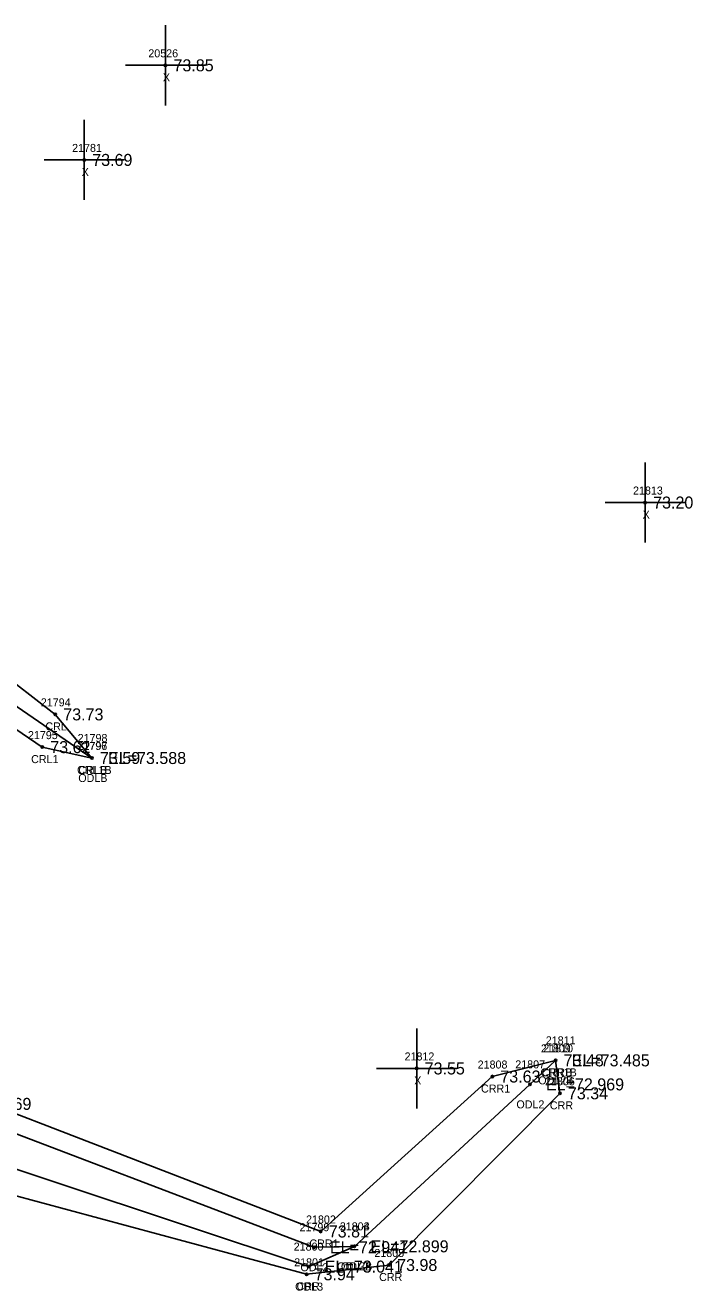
# Model space of a CAD drawing. Extents: x 2140110 to 2141565, y 506241 to 510327.
# Drawn here: x 2141122 to 2141205.4, y 508987.8 to 509145.9 of the extents above; entities that cross this region are included whole.
import ezdxf

# ---------------------------------------------------------------- set-up
doc = ezdxf.new("R2010")
doc.units = 0
for name, color, linetype in [('RD_EX_H2O', 7, 'Continuous'), ('RD_EX_H2O_txCode', 7, 'Continuous'), ('RD_EX_Misc', 7, 'Continuous'), ('RD_EX_Misc_txCode', 7, 'Continuous'), ('RD_EX_TX_H2O_ELEV', 7, 'Continuous'), ('RD_EX_TX_Misc_ELEV', 7, 'Continuous'), ('RD_SMD_Locator', 7, 'Continuous')]:
    doc.layers.add(name, color=color, linetype=linetype)

msp = doc.modelspace()

# ---------------------------------------------------------------- linework, layer by layer
at = {"layer": 'RD_EX_H2O'}
for points in [[(2140988.5, 509071.15), (2140995.33, 509067.35), (2140996.76, 509067.73), (2140999.1, 509067.34), (2141034.38, 509073.97), (2141067.92, 509085.44), (2141090.44, 509074.61), (2141110.47, 509071.64), (2141125.77, 509059.81), (2141130.36, 509054.36)], [(2140983.12, 509065.42), (2141000.37, 509063.93), (2141034.44, 509070.84), (2141066.81, 509082.08), (2141091.11, 509071.69), (2141109, 509069.02), (2141130.36, 509054.36)], [(2140983.12, 509065.42), (2140982.47, 509053.34), (2141000.94, 509051.84), (2141038.78, 509037.69), (2141057.55, 509016.17), (2141074.84, 509015.45), (2141078.58, 509016.54), (2141083.45, 509017.01), (2141111.03, 509011.14), (2141158.09, 508993.23), (2141163.15, 508993.34), (2141185.07, 509013.58), (2141188.28, 509016.58)], [(2141082.69, 509020.24), (2141075.54, 509038.17), (2141075.02, 509053.74), (2141081.95, 509060.99), (2141090.22, 509065.05), (2141109.63, 509065.58), (2141124.15, 509055.72), (2141130.36, 509054.36)], [(2140982.47, 509053.34), (2140997.59, 509046.83), (2141035.66, 509032.89), (2141054.88, 509012.31), (2141077.05, 509011.67), (2141109.94, 509006.62), (2141157.44, 508990.81), (2141163.15, 508993.34)], [(2140979.84, 509045.53), (2140988.49, 509044.65), (2140996.91, 509042.64), (2141034.47, 509029.98), (2141054.86, 509009.95), (2141076.5, 509008.6), (2141108.93, 509002.88), (2141157.17, 508989.85), (2141167.48, 508991.01), (2141188.81, 509012.46), (2141188.28, 509016.58)], [(2141082.69, 509020.24), (2141111.01, 509013.67), (2141158.94, 508995.2), (2141180.37, 509014.56), (2141188.28, 509016.58)]]:
    msp.add_lwpolyline(points, dxfattribs=at)
at = {"layer": 'RD_EX_Misc'}
for p, q in [((2141139.54, 509135.91), (2141139.54, 509145.91)), ((2141134.54, 509140.91), (2141144.54, 509140.91)), ((2141129.39, 509124.09), (2141129.39, 509134.09)), ((2141124.39, 509129.09), (2141134.39, 509129.09)), ((2141199.46, 509081.28), (2141199.46, 509091.28)), ((2141194.46, 509086.28), (2141204.46, 509086.28)), ((2141170.92, 509010.57), (2141170.92, 509020.57)), ((2141165.92, 509015.57), (2141175.92, 509015.57))]:
    msp.add_line(p, q, dxfattribs=at)
at = {"layer": 'RD_SMD_Locator'}
for centre in [(2141139.54, 509140.91), (2141129.39, 509129.09), (2141199.46, 509086.28), (2141125.77, 509059.81), (2141124.15, 509055.72), (2141130.36, 509054.36), (2141130.36, 509054.36), (2141130.36, 509054.36), (2141170.92, 509015.57), (2141188.28, 509016.58), (2141188.28, 509016.58), (2141188.28, 509016.58), (2141180.37, 509014.56), (2141185.07, 509013.58), (2141188.81, 509012.46), (2141158.94, 508995.2), (2141158.09, 508993.23), (2141163.15, 508993.34), (2141163.15, 508993.34), (2141157.44, 508990.81), (2141167.48, 508991.01), (2141157.17, 508989.85)]:
    msp.add_circle(centre, 0.15, dxfattribs=at)

# ---------------------------------------------------------------- texts
at = {"layer": 'RD_EX_H2O_txCode'}
for s, p in [('21794', (2141123.97, 509060.81)), ('CRL', (2141124.54, 509057.81)), ('21795', (2141122.36, 509056.72)), ('21798', (2141128.57, 509056.36)), ('21796', (2141128.54, 509055.36)), ('21797', (2141128.57, 509055.36)), ('CRL1', (2141122.76, 509053.72)), ('CRL1B', (2141128.5, 509052.36)), ('ODLB', (2141128.65, 509051.36)), ('CRLB', (2141128.66, 509052.36)), ('21811', (2141187.05, 509018.58)), ('21809', (2141186.44, 509017.58)), ('21810', (2141186.73, 509017.58)), ('21808', (2141178.54, 509015.56)), ('21807', (2141183.24, 509015.58)), ('CRR1B', (2141186.39, 509014.58)), ('CRRB', (2141186.55, 509014.58)), ('ODL2B', (2141186.11, 509013.58)), ('21806', (2141186.95, 509013.46)), ('CRR1', (2141178.96, 509012.56)), ('ODL2', (2141183.38, 509010.58)), ('CRR', (2141187.56, 509010.46)), ('21802', (2141157.1, 508996.2)), ('21799', (2141156.29, 508995.23)), ('21803', (2141161.32, 508995.34)), ('21804', (2141161.32, 508995.34)), ('21800', (2141155.56, 508992.81)), ('CRR1', (2141157.52, 508993.2)), ('21801', (2141155.62, 508990.85)), ('21805', (2141165.64, 508992.01)), ('ODL2', (2141156.4, 508990.23)), ('ODL3B', (2141160.98, 508990.34)), ('ODL2', (2141161.46, 508990.34)), ('ODL3', (2141155.74, 508987.81)), ('CRR', (2141155.92, 508987.85)), ('CRR', (2141166.23, 508989.01))]:
    msp.add_text(s, height=1, dxfattribs=at).set_placement(p)
at = {"layer": 'RD_EX_Misc_txCode'}
for s, p in [('20526', (2141137.4, 509141.91)), ('X', (2141139.22, 509138.91)), ('21781', (2141127.88, 509130.09)), ('X', (2141129.07, 509127.09)), ('21813', (2141197.95, 509087.28)), ('X', (2141199.15, 509084.28)), ('21812', (2141169.41, 509016.57)), ('X', (2141170.61, 509013.57))]:
    msp.add_text(s, height=1, dxfattribs=at).set_placement(p)
at = {"layer": 'RD_EX_TX_H2O_ELEV'}
for s, p in [('73.73', (2141126.77, 509059.06)), ('73.62', (2141125.15, 509054.97)), ('73.59', (2141131.36, 509053.61)), ('73.59', (2141131.36, 509053.61)), ('EL=73.588', (2141132.36, 509053.61)), ('73.48', (2141189.28, 509015.83)), ('73.48', (2141189.28, 509015.83)), ('EL=73.485', (2141190.28, 509015.83)), ('73.63', (2141181.37, 509013.81)), ('EL=72.969', (2141187.07, 509012.83)), ('73.34', (2141189.81, 509011.71)), ('EL=72.869', (2141113.03, 509010.39)), ('73.81', (2141159.94, 508994.45)), ('EL=72.941', (2141160.09, 508992.48)), ('EL=72.899', (2141165.15, 508992.59)), ('EL=72.899', (2141165.15, 508992.59)), ('73.98', (2141168.48, 508990.26)), ('73.94', (2141158.17, 508989.1)), ('EL=73.041', (2141159.44, 508990.06))]:
    msp.add_text(s, height=1.5, dxfattribs=at).set_placement(p)
at = {"layer": 'RD_EX_TX_Misc_ELEV'}
for s, p in [('73.85', (2141140.54, 509140.16)), ('73.69', (2141130.39, 509128.34)), ('73.20', (2141200.46, 509085.53)), ('73.55', (2141171.92, 509014.82))]:
    msp.add_text(s, height=1.5, dxfattribs=at).set_placement(p)

doc.saveas('drawing.dxf')
